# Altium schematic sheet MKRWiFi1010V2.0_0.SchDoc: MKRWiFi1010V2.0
size A3; Author: Arturo Guadalupi; SheetNumber: 1; SheetTotal: 2; RevAuthor: Francesca Cenna
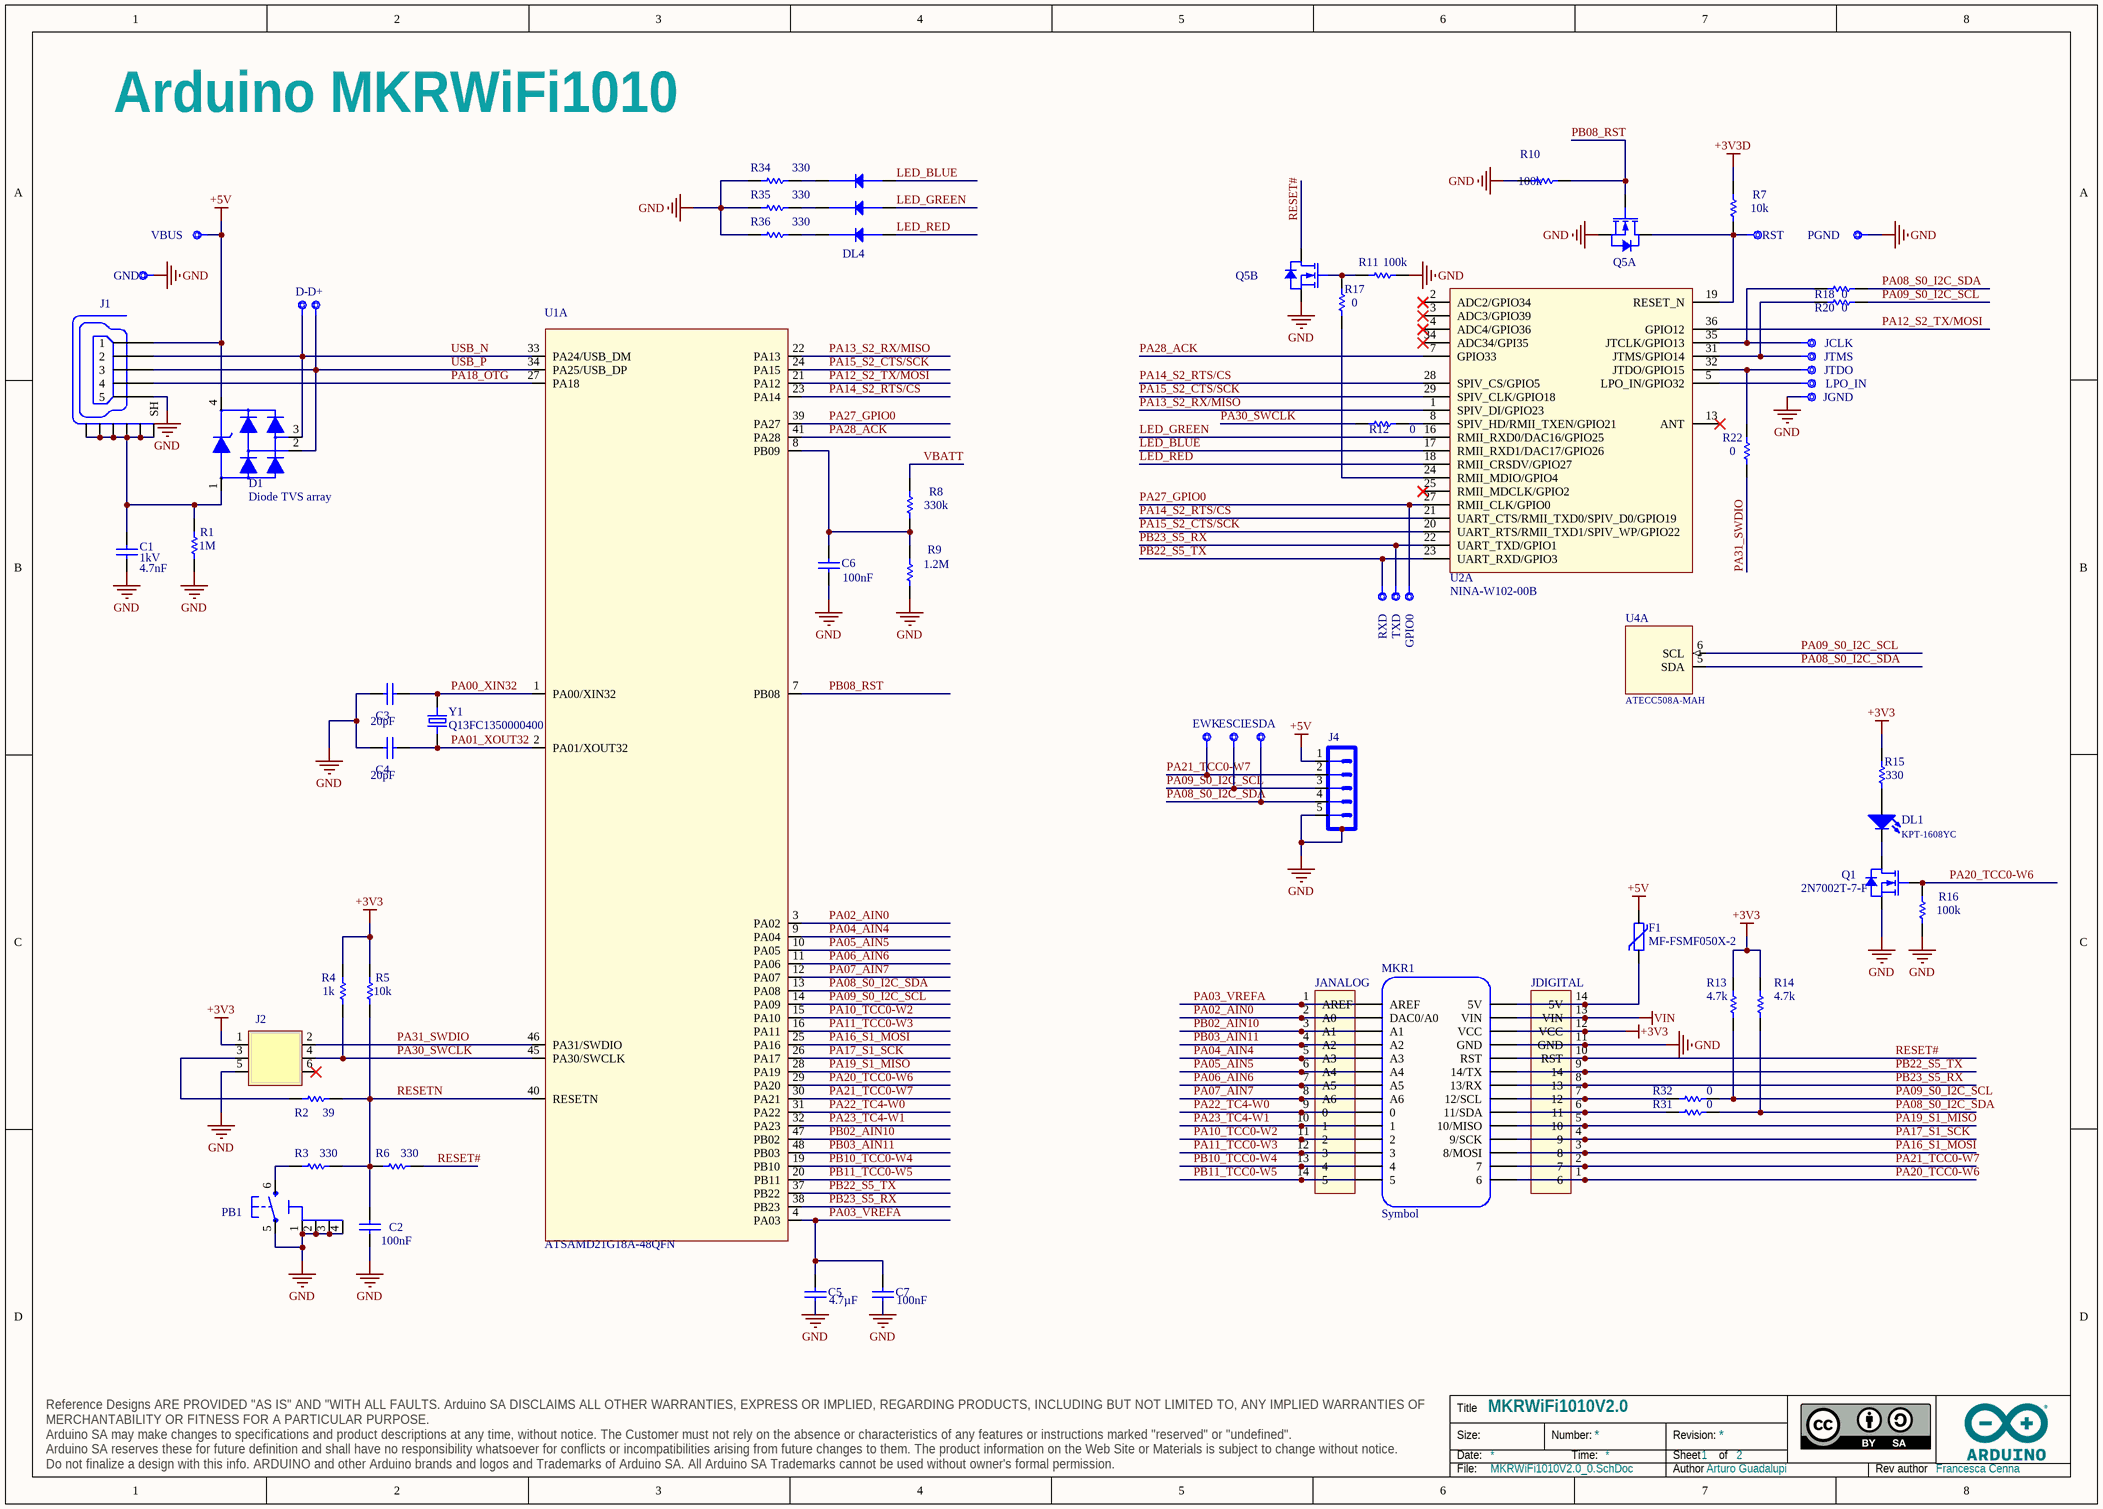
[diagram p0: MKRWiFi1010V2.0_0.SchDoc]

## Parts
C1  value 4.7nF  Voltage: 1kV  [CAP-0805]  (hidden comment: C0805C472KDRACTU)
C2  value 100nF  [CAP-0402]  (hidden comment: C0402C104K8PACTU)
C3  value 20pF  [CAP-0402]  (hidden comment: C0402C200J5GACTU)
C4  value 20pF  [CAP-0402]  (hidden comment: C0402C200J5GACTU)
C5  value 4.7µF  [CAP-0402]  (hidden comment: GRM155R60J475ME47D)
C6  value 100nF  [CAP-0402]  (hidden comment: C0402C104K8PACTU)
C7  value 100nF  [CAP-0402]  (hidden comment: C0402C104K8PACTU)
D1  Diode TVS array  [SOT190P230X110-4N]
D+  CMP-018-0005-A.3  [TP-1.00MM]  (value not drawn)  (no BOM)
D-  CMP-018-0005-A.3  [TP-1.00MM]  (value not drawn)  (no BOM)
DL1  KPT-1608YC  [LEDC1608X80N-AK]
DL4  LTRBGFSF-ABCB-QKYO  [RGBLED]  (value not drawn)
ESCL  CMP-018-0005-A.3  [TP-1.00MM]  (value not drawn)  (no BOM)
ESDA  CMP-018-0005-A.3  [TP-1.00MM]  (value not drawn)  (no BOM)
EWK  CMP-018-0005-A.3  [TP-1.00MM]  (value not drawn)  (no BOM)
F1  MF-FSMF050X-2  [0603]
GND  CMP-018-0005-A.3  [TP-1.00MM]  (value not drawn)  (no BOM)
GPIO0  CMP-018-0004-A.4  [TP-0.8MM]  (value not drawn)  (no BOM)
J1  ZX62-AB-5PA(31)  [ZX62-AB-5PA]  (value not drawn)
J2  PHD-2X03-DNP  [PHD-2X03-Footprint-1]  (value not drawn)
J4  21TW-287  [SM05B-SRSS-TB]  (value not drawn)
JANALOG  21TW-332  [21TW-332-Footprint-1]  (value not drawn)
JCLK  CMP-018-0004-A.4  [TP-0.8MM]  (value not drawn)  (no BOM)
JDIGITAL  21TW-331  [21TW-331-Footprint-1]  (value not drawn)
JGND  CMP-018-0004-A.4  [TP-0.8MM]  (value not drawn)  (no BOM)
JTDO  CMP-018-0004-A.4  [TP-0.8MM]  (value not drawn)  (no BOM)
JTMS  CMP-018-0004-A.4  [TP-0.8MM]  (value not drawn)  (no BOM)
LPO_IN  CMP-018-0005-A.3  [TP-1.00MM]  (value not drawn)  (no BOM)
MKR1  Symbol  [MKR-NOOUTLINE]  (no BOM)
PB1  PTS820J25KSMTRLFS  [C&K_PTS820_NO_HOLES-1]  (value not drawn)
PGND  CMP-018-0004-A.4  [TP-0.8MM]  (value not drawn)  (no BOM)
Q1  2N7002T-7-F  [SOT523]
Q5  CMP-017-0012-A.3  [SOT363]  (value not drawn)  (parts A,B of 2)
R1  value 1M  [RES-0402]  (hidden comment: CRCW04021M00JNED)
R2  value 39  [RES-0402]  (hidden comment: RC0402FR-0739RL)
R3  value 330  [RES-0402]  (hidden comment: CRCW0402330RJNED)
R4  value 1k  [RES-0402]  (hidden comment: CRCW04021K00FKEDC)
R5  value 10k  [RES-0402]  (hidden comment: CRCW040210K0FKED)
R6  value 330  [RES-0402]  (hidden comment: CRCW0402330RJNED)
R7  value 10k  [RES-0402]  (hidden comment: CRCW040210K0FKED)
R8  value 330k  [RES-0402]  (hidden comment: CRCW0402330KJNED)
R9  value 1.2M  [RES-0402]  (hidden comment: CRCW04021M20JNED)
R10  value 100k  [RES-0402]  (hidden comment: CRCW0402100KFKEDC)
R11  value 100k  [RES-0402]  (hidden comment: CRCW0402100KFKEDC)
R12  value 0  [RES-0402]  (hidden comment: CRCW04020000Z0EDC)
R13  value 4.7k  [RES-0402]  (hidden comment: RC0402FR-074K7L)
R14  value 4.7k  [RES-0402]  (hidden comment: RC0402FR-074K7L)
R15  value 330  [RES-0402]  (hidden comment: CRCW0402330RJNED)
R16  value 100k  [RES-0402]  (hidden comment: CRCW0402100KFKEDC)
R17  value 0  [RES-0402]  (hidden comment: CRCW04020000Z0EDC)
R18  value 0  [RES-0402]  (hidden comment: CRCW04020000Z0EDC)
R20  value 0  [RES-0402]  (hidden comment: CRCW04020000Z0EDC)
R22  value 0  [RES-0402]  (hidden comment: CRCW04020000Z0EDC)
R31  value 0  [RES-0402]  (hidden comment: CRCW04020000Z0EDC)
R32  value 0  [RES-0402]  (hidden comment: CRCW04020000Z0EDC)
R34  value 330  [RES-0402]  (hidden comment: CRCW0402330RJNED)
R35  value 330  [RES-0402]  (hidden comment: CRCW0402330RJNED)
R36  value 330  [RES-0402]  (hidden comment: CRCW0402330RJNED)
RST  CMP-018-0004-A.4  [TP-0.8MM]  (value not drawn)  (no BOM)
RXD  CMP-018-0004-A.4  [TP-0.8MM]  (value not drawn)  (no BOM)
TXD  CMP-018-0004-A.4  [TP-0.8MM]  (value not drawn)  (no BOM)
U1  Part Number: ATSAMD21G18A-48QFN  [QFN48]  (hidden comment: ATSAMD21G18A-48QFN-A.5)  (part A of 2)
U2  NINA-W102-00B  [NINA-W102]  (part A of 2)
U4  ATECC508A-MAH  [UDFN8]  (part A of 2)
VBUS  CMP-018-0005-A.3  [TP-1.00MM]  (value not drawn)  (no BOM)
Y1  Q13FC1350000400  [ABS07]

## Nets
+3V3: J2.1 JDIGITAL.12(VCC) MKR1.VCC R4.2 R5.2 R13.2 R14.2 R15.1
+3V3D: R7.2
+5V: D1.4 F1.2 J1.1 J4.1 VBUS.X
GND: C1.2 C2.1 C3.2 C4.2 C5.1 C6.1 C7.1 GND.X J1.5 J2.5 J4.5 J4.SH1(SH) J4.SH2(SH) JDIGITAL.11(GND) JGND.X MKR1.GND PB1.1 PB1.2 PB1.3 PB1.4 PB1.5 PGND.X Q1.S Q5.1(S) Q5.4(S) R1.1 R9.1 R10.2 R11.2 R16.1 R34.1 R35.1 R36.1
VIN: JDIGITAL.13(VIN) MKR1.VIN
LED_BLUE: DL4.2(RED_A) U2.17(RMII_RXD1/DAC17/GPIO26)
LED_GREEN: DL4.1(GREEN_A) U2.16(RMII_RXD0/DAC16/GPIO25)
LED_RED: DL4.3(BLUE_A) U2.18(RMII_CRSDV/GPIO27)
PA00_XIN32: C3.1 U1.1(PA00/XIN32) Y1.2
PA01_XOUT32: C4.1 U1.2(PA01/XOUT32) Y1.1
PA02_AIN0: JANALOG.2(A0) MKR1.A0(DAC0/A0) U1.3(PA02)
PA03_VREFA: C5.2 C7.2 JANALOG.1(AREF) MKR1.AREF U1.4(PA03)
PA04_AIN4: JANALOG.5(A3) MKR1.A3 U1.9(PA04)
PA05_AIN5: JANALOG.6(A4) MKR1.A4 U1.10(PA05)
PA06_AIN6: JANALOG.7(A5) MKR1.A5 U1.11(PA06)
PA07_AIN7: JANALOG.8(A6) MKR1.A6 U1.12(PA07)
PA08_S0_I2C_SDA: ESDA.X J4.4 R14.1 R18.2 R31.2 U1.13(PA08) U4.5(SDA)
PA09_S0_I2C_SCL: ESCL.X J4.3 R13.1 R20.2 R32.2 U1.14(PA09) U4.6(SCL)
PA10_TCC0-W2: JANALOG.11(2) MKR1.2 U1.15(PA10)
PA11_TCC0-W3: JANALOG.12(3) MKR1.3 U1.16(PA11)
PA12_S2_TX/MOSI: U1.21(PA12) U2.36(GPIO12)
PA13_S2_RX/MISO: U1.22(PA13) U2.1(SPIV_DI/GPIO23)
PA14_S2_RTS/CS: U1.23(PA14) U2.21(UART_CTS/RMII_TXD0/SPIV_D0/GPIO19) U2.28(SPIV_CS/GPIO5)
PA15_S2_CTS/SCK: U1.24(PA15) U2.20(UART_RTS/RMII_TXD1/SPIV_WP/GPIO22) U2.29(SPIV_CLK/GPIO18)
PA16_S1_MOSI: JDIGITAL.3(8) MKR1.8(8/MOSI) U1.25(PA16)
PA17_S1_SCK: JDIGITAL.4(9) MKR1.9(9/SCK) U1.26(PA17)
PA18_OTG: J1.4 U1.27(PA18)
PA19_S1_MISO: JDIGITAL.5(10) MKR1.10(10/MISO) U1.28(PA19)
PA20_TCC0-W6: JDIGITAL.1(6) MKR1.6 Q1.G R16.2 U1.29(PA20)
PA21_TCC0-W7: EWK.X J4.2 JDIGITAL.2(7) MKR1.7 U1.30(PA21)
PA22_TC4-W0: JANALOG.9(0) MKR1.0 U1.31(PA22)
PA23_TC4-W1: JANALOG.10(1) MKR1.1 U1.32(PA23)
PA27_GPIO0: GPIO0.X U1.39(PA27) U2.27(RMII_CLK/GPIO0)
PA28_ACK: U1.41(PA28) U2.7(GPIO33)
PA30_SWCLK: J2.4 R4.1 R12.1 U1.45(PA30/SWCLK)
PA31_SWDIO: J2.2 R22.1 U1.46(PA31/SWDIO)
PB02_AIN10: JANALOG.3(A1) MKR1.A1 U1.47(PB02)
PB03_AIN11: JANALOG.4(A2) MKR1.A2 U1.48(PB03)
PB08_RST: Q5.2(G) R10.1 U1.7(PB08)
PB10_TCC0-W4: JANALOG.13(4) MKR1.4 U1.19(PB10)
PB11_TCC0-W5: JANALOG.14(5) MKR1.5 U1.20(PB11)
PB22_S5_TX: JDIGITAL.9(14) MKR1.14(14/TX) RXD.X U1.37(PB22) U2.23(UART_RXD/GPIO3)
PB23_S5_RX: JDIGITAL.8(13) MKR1.13(13/RX) TXD.X U1.38(PB23) U2.22(UART_TXD/GPIO1)
RESET#: JDIGITAL.10(RST) MKR1.RST Q5.3(D) R6.2
RESETN: C2.2 R2.2 R3.2 R5.1 R6.1 U1.40(RESETN)
USB_N: D1.3 D-.X J1.2 U1.33(PA24/USB_DM)
USB_P: D1.2 D+.X J1.3 U1.34(PA25/USB_DP)
VBATT: R8.2
NetC1_1: C1.1 D1.1 J1.M1(SH) J1.M2(SH) J1.M3(SH) J1.M4(SH) J1.M5(SH) J1.M6(SH) R1.2
NetC6_2: C6.2 R8.1 R9.2 U1.8(PB09)
NetDL1_A: DL1.A R15.2
NetDL1_C: DL1.C Q1.D
NetDL4_4: DL4.4(BLUE_C) R36.2
NetDL4_5: DL4.5(RED_C) R34.2
NetDL4_6: DL4.6(GREEN_C) R35.2
NetF1_1: F1.1 JDIGITAL.14(5V) MKR1.5V
NetJ2_3: J2.3 R2.1
NetJCLK_X: JCLK.X R18.1 U2.35(JTCLK/GPIO13)
NetJDIGITAL_6: JDIGITAL.6(11) MKR1.11(11/SDA) R31.1
NetJDIGITAL_7: JDIGITAL.7(12) MKR1.12(12/SCL) R32.1
NetJTDO_X: JTDO.X R22.2 U2.32(JTDO/GPIO15)
NetJTMS_X: JTMS.X R20.1 U2.31(JTMS/GPIO14)
NetLPO_IN_X: LPO_IN.X U2.5(LPO_IN/GPIO32)
NetPB1_6: PB1.6 R3.1
NetQ5_5: Q5.5(G) R11.1 R17.2
NetQ5_6: Q5.6(D) R7.1 RST.X U2.19(RESET_N)
NetR12_2: R12.2 U2.8(SPIV_HD/RMII_TXEN/GPIO21)
NetR17_1: R17.1 U2.24(RMII_MDIO/GPIO4)

Not connected (* = marked no-connect by the designer): J2 6*; U2 2(ADC2/GPIO34)* 3(ADC3/GPIO39)* 4(ADC4/GPIO36)* 13(ANT)* 25(RMII_MDCLK/GPIO2)* 34(ADC34/GPI35)*

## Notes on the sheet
- Arduino MKRWiFi1010

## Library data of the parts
C1 = C0059-A.3: CAP CHIP 0805 4.7nF 1000V X7R 10%; Manufacturer: KEMET; Code Arduino: 0689
C2 C6 C7 = C0011-A.3: CAP CHIP 0402 100nf 10V X5R 10%; Manufacturer: KEMET; Code Arduino: 0132
C3 C4 = C0027-A.3: CAP CHIP 0402 20pF 50V C0G 5%; Manufacturer: KEMET; Code Arduino: 2188
C5 = C0037-A.3: CAP CHIP 0402 4.7uF 6V3 X5R 20%; Manufacturer: Murata; Code Arduino: 0833; Voltage: 6.3V
D1 = D0025-A.2: TVS ARRAY 4LIN.8kV 1pF SOT143B; Part Number: PRTR5V0U2X,215; Manufacturer: Nexperia; Code Arduino: 2209; Device Type: ESD protection
D+ D- ESCL ESDA EWK GND LPO_IN VBUS = UT0013-A.1: Test point 1.00mm
DL1 = L0008-A.2: LED SMD 0603 GIA588   8mcd 120^; Manufacturer: Kingbright; Code Arduino: 2243
DL4 = L0015-A.2: LED SMDPLCC6 RGB 625-530-460nm; Manufacturer: OSRAM; Code Arduino: 2211
F1 = P0000-A.2: PTC SMD 0603 RESET FUSE 6V 0.5A; Manufacturer: Bourns; Code Arduino: 2217; Voltage: 40V; Current: 500mA
GPIO0 JCLK JGND JTDO JTMS PGND RST RXD TXD = UT0012-A.1: Test point 0.8mm
J1 = J0039-A.2: CONN USB MICRO F/90^ SMD TipoAB 5x1; Manufacturer: Hirose; Code Arduino: 2219
J2 = J0000-A.2: CONN SMD 2X03, DNP
J4 = J0034-A.1: CONN HEADER SMD R/A 5POS 1MM WIRE-BOARD; Code Arduino: 2353
JANALOG = J0048-A.2: CONN STRIP F/M 14x1 PITCH 2.54 MKR SHIELD AREF; Code Arduino: A5273
JDIGITAL = J0047-A.2: CONN STRIP F/M 14x1 PITCH 2.54 MKR SHIELD 5V; Code Arduino: A5272
MKR1 = UT0007-A.1: MKR board without outline
PB1 = B0006-A.4: PUSHBUTTON SMD PTS820 NO HOLES; Manufacturer: C&K; Code Arduino: A5506; Mechanical Life: 100000Cycles; Actuator Type: Standard
Q1 = T0003-A.1: MOSFET N-CH 60V 115mA SOT523; Manufacturer: Diodes Inc.; Code Arduino: 2368; Device Type: Mosfet N-CH SMD
Q5 = T0012-A.1: MOSFET N-CH 2x 60V 0.32A SOT363; Part Number: BSS138PS; Code Arduino: 2323; Device Type: Mosfet 2N-CH SMD
R1 = R0006-A.3: RES CHIP 0402 1M 5% 1/16W; Code Arduino: 0139; Power: 63mW
R2 = R0005-A.3: RES CHIP 0402 39R 1% 1/16W; Manufacturer: Yageo; Code Arduino: 0138; Power: 63mW
R3 R6 R15 R34-R36 = R0017-A.3: RES CHIP 0402 330R 5% 1/16W; Manufacturer: Vishay; Code Arduino: 2229; Power: 63mW
R4 = R0007-A.3: RES CHIP 0402 1K 1% 1/16W; Manufacturer: Vishay; Code Arduino: 0140; Power: 63mW
R5 R7 = R0003-A.3: RES CHIP 0402 10K 1% 1/16W; Manufacturer: Vishay; Code Arduino: 0136; Power: 63mW
R8 = R0011-A.3: RES CHIP 0402 330K 1% 1/16W; Manufacturer: Vishay; Code Arduino: 2192; Tolerance: 5%; Power: 63mW
R9 = R0022-A.3: RES CHIP 0402 1M2 5% 1/16W; Manufacturer: Vishay; Code Arduino: 2352; Power: 63mW
R10 R11 R16 = R0001-A.3: RES CHIP 0402 100K 1% 1/16W; Manufacturer: Vishay; Code Arduino: 0134; Power: 63mW
R12 R17 R18 R20 R22 R31 R32 = R0000-A.3: RES CHIP 0402 0R 1/16W; Manufacturer: Vishay; Code Arduino: 0039; Tolerance: J; Power: 63mW
R13 R14 = R0013-A.3: RES CHIP 0402 4K7 1% 1/16W; Manufacturer: Yageo; Code Arduino: 2196; Power: 63mW
U1 = U0041-A.2: IC ATSAMD21G18A-48QFN; Manufacturer: Microchip
U2 = M0002-A.2: MODULE ESP32 WiFi/BLE; Manufacturer: UBlox
U4 = U0033-A.2: IC CRYPTO PROC.256b  UDFN8; Manufacturer: Microchip; Code Arduino: ATECC508A-MAHDA-T8-UDFN
Y1 = X0003-A.2: CRYSTAL SMD 32,768K3,2x1,5H,9RoHS; Manufacturer: Epson; Code Arduino: 0213; Frequency: 32.768kHz; Frequency Tolerance: 20ppm; Load Capacitance: 12.5pF; Series Resistance: 70kR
